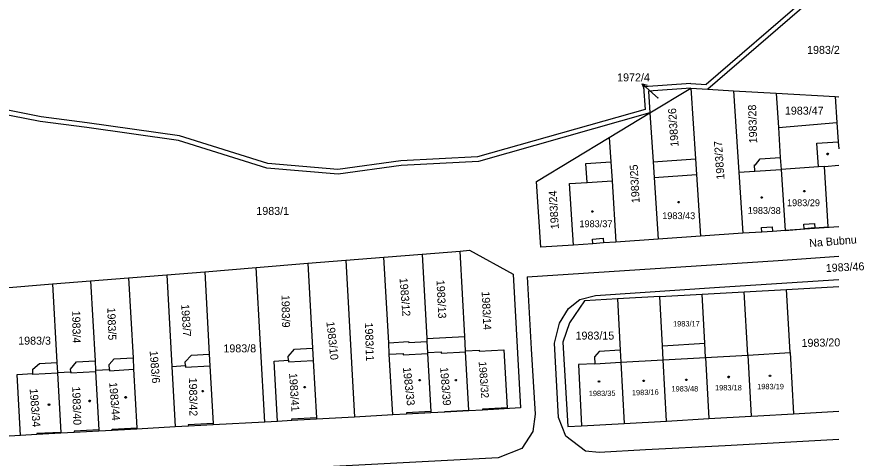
# Model space of a CAD drawing. Extents: x -621797 to -620972, y -1175539 to -1174697.
# Drawn here: x -621151.7 to -620971.8, y -1174978.1 to -1174884.4 of the extents above; entities that cross this region are included whole.
import ezdxf

# ---------------------------------------------------------------- set-up
doc = ezdxf.new("R2010")
doc.units = 0
for name, color, linetype in [('INZ mimo EON - nadz', 7, 'Continuous'), ('Rozvod plynu EON', 7, 'Continuous'), ('SDEL EON - popis', 7, 'Continuous'), ('Silnoproud EON', 7, 'Continuous'), ('Silnoproud EON - popis', 7, 'Continuous')]:
    doc.layers.add(name, color=color, linetype=linetype)

msp = doc.modelspace()

# ---------------------------------------------------------------- linework, layer by layer
at = {"layer": 'INZ mimo EON - nadz'}
for p in [(-621018.904, -1174898.566), (-621015.51, -1174901.63)]:
    msp.add_line(p, (-621016.68, -1174900.58), dxfattribs=at)
msp.add_lwpolyline([(-621018.498, -1174899.608), (-621018.904, -1174898.566), (-621017.827, -1174898.867)], dxfattribs=at)
at = {"layer": 'Rozvod plynu EON'}
for points in [[(-620979.43, -1174913.35), (-620979.34, -1174913.5), (-620979.43, -1174913.65), (-620979.61, -1174913.65), (-620979.7, -1174913.5), (-620979.61, -1174913.35)], [(-620984.37, -1174921.26), (-620984.28, -1174921.41), (-620984.37, -1174921.56), (-620984.55, -1174921.56), (-620984.64, -1174921.41), (-620984.55, -1174921.26)], [(-621011.08, -1174923.58), (-621010.99, -1174923.73), (-621011.08, -1174923.88), (-621011.26, -1174923.88), (-621011.35, -1174923.73), (-621011.26, -1174923.58)], [(-620993.39, -1174922.61), (-620993.3, -1174922.76), (-620993.39, -1174922.91), (-620993.57, -1174922.91), (-620993.66, -1174922.76), (-620993.57, -1174922.61)], [(-621029.36, -1174925.58), (-621029.27, -1174925.73), (-621029.36, -1174925.88), (-621029.54, -1174925.88), (-621029.63, -1174925.73), (-621029.54, -1174925.58)], [(-621066.05, -1174961.4), (-621065.96, -1174961.55), (-621066.05, -1174961.7), (-621066.23, -1174961.7), (-621066.32, -1174961.55), (-621066.23, -1174961.4)], [(-621058.36, -1174961.4), (-621058.27, -1174961.55), (-621058.36, -1174961.7), (-621058.54, -1174961.7), (-621058.63, -1174961.55), (-621058.54, -1174961.4)], [(-621027.97, -1174961.73), (-621027.88, -1174961.88), (-621027.97, -1174962.03), (-621028.15, -1174962.03), (-621028.24, -1174961.88), (-621028.15, -1174961.73)], [(-621018.5, -1174961.55), (-621018.41, -1174961.7), (-621018.5, -1174961.85), (-621018.68, -1174961.85), (-621018.77, -1174961.7), (-621018.68, -1174961.55)], [(-621009.43, -1174961.36), (-621009.34, -1174961.51), (-621009.43, -1174961.66), (-621009.61, -1174961.66), (-621009.7, -1174961.51), (-621009.61, -1174961.36)], [(-621000.46, -1174960.76), (-621000.37, -1174960.91), (-621000.46, -1174961.06), (-621000.64, -1174961.06), (-621000.73, -1174960.91), (-621000.64, -1174960.76)], [(-620991.67, -1174960.48), (-620991.58, -1174960.63), (-620991.67, -1174960.78), (-620991.85, -1174960.78), (-620991.94, -1174960.63), (-620991.85, -1174960.48)], [(-621090.5, -1174962.94), (-621090.41, -1174963.09), (-621090.5, -1174963.24), (-621090.68, -1174963.24), (-621090.77, -1174963.09), (-621090.68, -1174962.94)], [(-621128.5, -1174965.07), (-621128.41, -1174965.22), (-621128.5, -1174965.37), (-621128.68, -1174965.37), (-621128.77, -1174965.22), (-621128.68, -1174965.07)], [(-621112.12, -1174963.75), (-621112.03, -1174963.9), (-621112.12, -1174964.05), (-621112.3, -1174964.05), (-621112.39, -1174963.9), (-621112.3, -1174963.75)], [(-621144.78, -1174966.63), (-621144.69, -1174966.78), (-621144.78, -1174966.93), (-621144.96, -1174966.93), (-621145.05, -1174966.78), (-621144.96, -1174966.63)], [(-621136.17, -1174965.86), (-621136.08, -1174966.01), (-621136.17, -1174966.16), (-621136.35, -1174966.16), (-621136.44, -1174966.01), (-621136.35, -1174965.86)]]:
    msp.add_lwpolyline(points, close=True, dxfattribs=at)
at = {"layer": 'SDEL EON - popis'}
for p, q in [((-620984.41, -1174880.64), (-621005.32, -1174898.72)), ((-621008.55, -1174898.53), (-621018.59, -1174899.19)), ((-621008.55, -1174898.53), (-621005.32, -1174898.72)), ((-621018.59, -1174899.19), (-621018.28, -1174904.03)), ((-621146.57, -1174905.58), (-621155.92, -1174903.76)), ((-621018.28, -1174904.03), (-621053.84, -1174914.11)), ((-621136.73, -1174906.87), (-621146.57, -1174905.58)), ((-621117.18, -1174909.65), (-621136.73, -1174906.87)), ((-621098.42, -1174915.51), (-621117.18, -1174909.65)), ((-620981.79, -1174911.23), (-620977.25, -1174910.88)), ((-620981.41, -1174916.22), (-620981.79, -1174911.23)), ((-621070.16, -1174914.95), (-621083.51, -1174916.76)), ((-621053.84, -1174914.11), (-621070.16, -1174914.95)), ((-621083.51, -1174916.76), (-621098.42, -1174915.51)), ((-620981.41, -1174916.22), (-620989.38, -1174916.78)), ((-620980.2, -1174916.14), (-620981.41, -1174916.22)), ((-620980.2, -1174916.14), (-620977.15, -1174915.88)), ((-620979.37, -1174928.97), (-620980.2, -1174916.14)), ((-621016.33, -1174918.48), (-621007.35, -1174917.88)), ((-620994.97, -1174917.16), (-620989.38, -1174916.78)), ((-621030.58, -1174919.54), (-621025.29, -1174919.2)), ((-620993.52, -1174929.1), (-620991.29, -1174928.95)), ((-620993.45, -1174930.09), (-620993.52, -1174929.1)), ((-620991.29, -1174928.95), (-620991.22, -1174929.95)), ((-620984.58, -1174928.44), (-620982.29, -1174928.26)), ((-620984.5, -1174929.42), (-620984.58, -1174928.44)), ((-620982.21, -1174929.22), (-620984.5, -1174929.42)), ((-620982.29, -1174928.26), (-620982.21, -1174929.22)), ((-620982.21, -1174929.22), (-620979.37, -1174928.97)), ((-620988.53, -1174929.77), (-620984.5, -1174929.42)), ((-621029.46, -1174931.57), (-621027.18, -1174931.42)), ((-621029.39, -1174932.57), (-621029.46, -1174931.57)), ((-621027.18, -1174931.42), (-621027.12, -1174932.41)), ((-621072.59, -1174956.04), (-621069.66, -1174955.88)), ((-621069.66, -1174955.88), (-621069.65, -1174956.22)), ((-621069.65, -1174956.22), (-621064.48, -1174955.93)), ((-621064.49, -1174955.73), (-621061.56, -1174955.58)), ((-621061.56, -1174955.58), (-621061.55, -1174955.84)), ((-621061.55, -1174955.84), (-621056.4, -1174955.53)), ((-621005.44, -1174956.73), (-620996.47, -1174956.23)), ((-620996.47, -1174956.23), (-620987.48, -1174955.73)), ((-621094.02, -1174957.36), (-621094, -1174957.71)), ((-621094, -1174957.71), (-621088.74, -1174957.42)), ((-621028.96, -1174958.09), (-621023.42, -1174957.78)), ((-621023.42, -1174957.78), (-621014.43, -1174957.26)), ((-621014.43, -1174957.26), (-621005.44, -1174956.73)), ((-621140.26, -1174959.77), (-621140.24, -1174960.03)), ((-621140.24, -1174960.03), (-621134.98, -1174959.74)), ((-621132.04, -1174959.28), (-621132.03, -1174959.58)), ((-621132.03, -1174959.58), (-621126.89, -1174959.25)), ((-621115.91, -1174958.49), (-621115.9, -1174958.79)), ((-621115.9, -1174958.79), (-621110.71, -1174958.5)), ((-621148.27, -1174960.4), (-621148.28, -1174960.15)), ((-621143.07, -1174960.11), (-621148.27, -1174960.4)), ((-621063.8, -1174968.23), (-621068.96, -1174968.51)), ((-621068.96, -1174968.51), (-621068.94, -1174968.81)), ((-621060.82, -1174968.22), (-621055.71, -1174967.93)), ((-621060.82, -1174968.36), (-621060.82, -1174968.22)), ((-621088.07, -1174969.57), (-621093.34, -1174969.86)), ((-621093.34, -1174969.86), (-621093.32, -1174970.16)), ((-621134.3, -1174972.13), (-621139.51, -1174972.42)), ((-621139.51, -1174972.42), (-621139.5, -1174972.71)), ((-621131.46, -1174971.97), (-621126.21, -1174971.68)), ((-621131.45, -1174972.27), (-621131.46, -1174971.97)), ((-621110.04, -1174970.78), (-621115.28, -1174971.08)), ((-621115.28, -1174971.08), (-621115.27, -1174971.37)), ((-621142.38, -1174972.67), (-621147.47, -1174972.88)), ((-621147.47, -1174972.88), (-621147.46, -1174973.15))]:
    msp.add_line(p, q, dxfattribs=at)
at = {"layer": 'Silnoproud EON'}
for p, q in [((-620983.45, -1174881.13), (-621004.97, -1174899.74)), ((-621008.55, -1174899.53), (-621017.53, -1174900.12)), ((-621017.53, -1174900.12), (-621017.23, -1174904.77)), ((-621017.23, -1174904.77), (-621008.55, -1174899.53)), ((-621008.55, -1174899.53), (-621004.97, -1174899.74)), ((-621008.55, -1174899.53), (-621007.57, -1174914.56)), ((-621004.97, -1174899.74), (-620999.5, -1174900.06)), ((-620999.5, -1174900.06), (-620990.45, -1174900.58)), ((-620999.5, -1174900.06), (-620998.36, -1174917.38)), ((-620990.45, -1174900.58), (-620977.89, -1174901.3)), ((-620990.45, -1174900.58), (-620989.97, -1174907.83)), ((-620977.89, -1174901.3), (-620977.15, -1174901.342)), ((-620977.89, -1174901.3), (-620977.52, -1174906.82)), ((-621146.73, -1174906.57), (-621156.07, -1174904.75)), ((-621017.23, -1174904.77), (-621053.68, -1174915.1)), ((-621025.89, -1174910), (-621017.23, -1174904.77)), ((-621017.23, -1174904.77), (-621016.55, -1174915.19)), ((-621136.87, -1174907.86), (-621146.73, -1174906.57)), ((-620989.97, -1174907.83), (-620977.52, -1174906.82)), ((-620977.52, -1174906.82), (-620977.25, -1174910.88)), ((-621117.4, -1174910.63), (-621136.87, -1174907.86)), ((-620989.97, -1174907.83), (-620989.55, -1174914.24)), ((-621098.61, -1174916.5), (-621117.4, -1174910.63)), ((-621041.3, -1174919.31), (-621025.89, -1174910)), ((-621025.89, -1174910), (-621025.56, -1174915.16)), ((-620977.25, -1174910.88), (-620977.15, -1174912.389)), ((-621016.55, -1174915.19), (-621007.57, -1174914.56)), ((-621007.57, -1174914.56), (-621007.35, -1174917.88)), ((-620994.81, -1174915.81), (-620993.81, -1174914.52)), ((-620993.81, -1174914.52), (-620989.55, -1174914.24)), ((-620989.55, -1174914.24), (-620989.38, -1174916.78)), ((-621083.48, -1174917.77), (-621098.61, -1174916.5)), ((-621070.07, -1174915.95), (-621083.48, -1174917.77)), ((-621053.68, -1174915.1), (-621070.07, -1174915.95)), ((-621030.85, -1174915.5), (-621025.56, -1174915.16)), ((-621030.58, -1174919.54), (-621030.85, -1174915.5)), ((-621025.56, -1174915.16), (-621025.29, -1174919.2)), ((-621016.55, -1174915.19), (-621016.33, -1174918.48)), ((-620995.06, -1174915.83), (-620994.81, -1174915.81)), ((-620994.97, -1174917.16), (-620995.06, -1174915.83)), ((-621016.33, -1174918.48), (-621015.47, -1174931.62)), ((-621007.35, -1174917.88), (-621006.49, -1174930.97)), ((-620998.36, -1174917.38), (-620994.97, -1174917.16)), ((-620998.36, -1174917.38), (-620997.51, -1174930.36)), ((-620989.38, -1174916.78), (-620988.53, -1174929.77)), ((-621040.42, -1174933.33), (-621041.3, -1174919.31)), ((-621034.34, -1174919.78), (-621030.58, -1174919.54)), ((-621033.48, -1174932.85), (-621034.34, -1174919.78)), ((-621025.29, -1174919.2), (-621024.45, -1174932.23)), ((-620977.15, -1174928.986), (-620988.53, -1174929.77)), ((-621006.49, -1174930.97), (-621015.47, -1174931.62)), ((-620997.51, -1174930.36), (-621006.49, -1174930.97)), ((-620993.45, -1174930.09), (-620997.51, -1174930.36)), ((-620991.22, -1174929.95), (-620993.45, -1174930.09)), ((-620988.53, -1174929.77), (-620991.22, -1174929.95)), ((-621033.48, -1174932.85), (-621040.42, -1174933.33)), ((-621029.39, -1174932.57), (-621033.48, -1174932.85)), ((-621027.12, -1174932.41), (-621029.39, -1174932.57)), ((-621024.45, -1174932.23), (-621027.12, -1174932.41)), ((-621015.47, -1174931.62), (-621024.45, -1174932.23)), ((-621065.65, -1174934.79), (-621057.58, -1174934.13)), ((-621057.58, -1174934.13), (-621055.58, -1174933.97)), ((-621056.58, -1174952.3), (-621057.58, -1174934.13)), ((-621055.58, -1174933.97), (-621046.29, -1174939.02)), ((-621089.88, -1174936.74), (-621081.8, -1174936.09)), ((-621081.8, -1174936.09), (-621073.73, -1174935.45)), ((-621081.8, -1174936.09), (-621079.96, -1174969.42)), ((-621073.73, -1174935.45), (-621065.65, -1174934.79)), ((-621072.72, -1174953.63), (-621073.73, -1174935.45)), ((-621065.65, -1174934.79), (-621064.66, -1174952.71)), ((-621043.3, -1174939.63), (-620989.98, -1174936.11)), ((-620989.98, -1174936.11), (-620977.15, -1174935.228)), ((-621111.81, -1174938.52), (-621100.85, -1174937.63)), ((-621100.85, -1174937.63), (-621089.88, -1174936.74)), ((-621099.03, -1174970.48), (-621100.85, -1174937.63)), ((-621089.88, -1174936.74), (-621088.88, -1174954.78)), ((-621136.04, -1174940.48), (-621127.96, -1174939.83)), ((-621127.96, -1174939.83), (-621119.88, -1174939.17)), ((-621127.96, -1174939.83), (-621127.02, -1174956.85)), ((-621119.88, -1174939.17), (-621111.81, -1174938.52)), ((-621119.88, -1174939.17), (-621118.81, -1174958.65)), ((-621111.81, -1174938.52), (-621110.85, -1174956.05)), ((-621046.29, -1174939.02), (-621044.72, -1174967.47)), ((-621043.3, -1174939.63), (-621042.46, -1174954.9)), ((-621155.09, -1174942.02), (-621144.12, -1174941.13)), ((-621144.12, -1174941.13), (-621136.04, -1174940.48)), ((-621144.12, -1174941.13), (-621143.2, -1174957.8)), ((-621136.04, -1174940.48), (-621135.1, -1174957.44)), ((-621028.81, -1174943.58), (-621002.46, -1174941.84)), ((-621002.46, -1174941.84), (-620977.15, -1174940.162)), ((-620988.22, -1174942.27), (-620977.15, -1174941.631)), ((-621032.11, -1174944.44), (-621028.81, -1174943.58)), ((-621015.17, -1174943.81), (-621006.18, -1174943.3)), ((-621006.18, -1174943.3), (-620997.21, -1174942.78)), ((-621005.61, -1174953.73), (-621006.18, -1174943.3)), ((-620997.21, -1174942.78), (-620988.22, -1174942.27)), ((-620996.47, -1174956.23), (-620997.21, -1174942.78)), ((-620987.48, -1174955.73), (-620988.22, -1174942.27)), ((-621034.54, -1174946.32), (-621032.11, -1174944.44)), ((-621031.14, -1174944.71), (-621034.35, -1174949.41)), ((-621024.16, -1174944.31), (-621031.14, -1174944.71)), ((-621015.17, -1174943.81), (-621024.16, -1174944.31)), ((-621024.16, -1174944.31), (-621023.56, -1174955.21)), ((-621014.6, -1174954.25), (-621015.17, -1174943.81)), ((-621036.43, -1174949.44), (-621034.54, -1174946.32)), ((-621037.52, -1174953.74), (-621036.43, -1174949.44)), ((-621034.35, -1174949.41), (-621035.71, -1174953.47)), ((-621064.66, -1174952.71), (-621056.58, -1174952.3)), ((-621064.66, -1174952.71), (-621064.63, -1174953.35)), ((-621056.41, -1174955.33), (-621056.58, -1174952.3)), ((-621072.72, -1174953.63), (-621068.49, -1174953.36)), ((-621072.59, -1174956.04), (-621072.72, -1174953.63)), ((-621068.49, -1174953.36), (-621068.46, -1174953.56)), ((-621068.46, -1174953.56), (-621064.63, -1174953.35)), ((-621064.63, -1174953.35), (-621064.49, -1174955.73)), ((-621036.68, -1174969.5), (-621037.52, -1174953.74)), ((-621035.71, -1174953.47), (-621034.69, -1174971.44)), ((-621014.6, -1174954.25), (-621005.61, -1174953.73)), ((-621014.43, -1174957.26), (-621014.6, -1174954.25)), ((-621005.44, -1174956.73), (-621005.61, -1174953.73)), ((-621115.96, -1174957.71), (-621114.61, -1174956.25)), ((-621114.61, -1174956.25), (-621110.85, -1174956.05)), ((-621110.85, -1174956.05), (-621110.71, -1174958.5)), ((-621094.06, -1174956.58), (-621092.7, -1174954.99)), ((-621092.7, -1174954.99), (-621088.88, -1174954.78)), ((-621088.88, -1174954.78), (-621088.74, -1174957.42)), ((-621071.88, -1174968.97), (-621072.59, -1174956.04)), ((-621064.49, -1174955.73), (-621064.48, -1174955.93)), ((-621064.48, -1174955.93), (-621063.8, -1174968.23)), ((-621056.41, -1174955.33), (-621053.54, -1174955.17)), ((-621056.4, -1174955.53), (-621056.41, -1174955.33)), ((-621055.71, -1174967.93), (-621056.4, -1174955.53)), ((-621053.54, -1174955.17), (-621053.53, -1174955.41)), ((-621053.53, -1174955.41), (-621048.25, -1174955.12)), ((-621048.25, -1174955.12), (-621047.54, -1174967.48)), ((-621042.46, -1174954.9), (-621041.64, -1174968.78)), ((-621028.05, -1174955.46), (-621029.04, -1174956.61)), ((-621023.56, -1174955.21), (-621028.05, -1174955.46)), ((-621023.56, -1174955.21), (-621023.42, -1174957.78)), ((-620996.47, -1174956.23), (-620995.75, -1174969.24)), ((-620987.48, -1174955.73), (-620986.76, -1174968.73)), ((-621148.33, -1174959.24), (-621146.92, -1174958.01)), ((-621146.92, -1174958.01), (-621143.2, -1174957.8)), ((-621143.2, -1174957.8), (-621143.08, -1174959.93)), ((-621140.29, -1174959.22), (-621139.05, -1174957.66)), ((-621139.05, -1174957.66), (-621135.1, -1174957.44)), ((-621135.1, -1174957.44), (-621135, -1174959.44)), ((-621132.1, -1174958.22), (-621131.02, -1174957.07)), ((-621131.02, -1174957.07), (-621127.02, -1174956.85)), ((-621127.02, -1174956.85), (-621126.89, -1174959.25)), ((-621115.91, -1174958.49), (-621115.96, -1174957.71)), ((-621097.02, -1174957.53), (-621094.02, -1174957.36)), ((-621096.36, -1174970.33), (-621097.02, -1174957.53)), ((-621094.02, -1174957.36), (-621094.06, -1174956.58)), ((-621088.74, -1174957.42), (-621088.07, -1174969.57)), ((-621028.96, -1174958.09), (-621032.44, -1174958.23)), ((-621029.04, -1174956.61), (-621028.96, -1174958.09)), ((-621023.42, -1174957.78), (-621022.71, -1174970.76)), ((-621013.72, -1174970.27), (-621014.43, -1174957.26)), ((-621005.44, -1174956.73), (-621004.73, -1174969.76)), ((-621148.28, -1174960.15), (-621148.33, -1174959.24)), ((-621143.08, -1174959.93), (-621140.26, -1174959.77)), ((-621143.08, -1174959.93), (-621143.07, -1174960.11)), ((-621140.26, -1174959.77), (-621140.29, -1174959.22)), ((-621135, -1174959.44), (-621132.04, -1174959.28)), ((-621135, -1174959.44), (-621134.98, -1174959.74)), ((-621134.98, -1174959.74), (-621134.3, -1174972.13)), ((-621132.04, -1174959.28), (-621132.1, -1174958.22)), ((-621126.89, -1174959.25), (-621126.21, -1174971.68)), ((-621118.81, -1174958.65), (-621115.91, -1174958.49)), ((-621118.81, -1174958.65), (-621118.1, -1174971.53)), ((-621110.71, -1174958.5), (-621110.04, -1174970.78)), ((-621032.44, -1174958.23), (-621031.76, -1174971.28)), ((-621151.64, -1174960.36), (-621148.28, -1174960.15)), ((-621150.91, -1174973.34), (-621151.64, -1174960.36)), ((-621143.07, -1174960.11), (-621142.38, -1174972.67)), ((-621068.94, -1174968.81), (-621071.88, -1174968.97)), ((-621063.79, -1174968.53), (-621068.94, -1174968.81)), ((-621063.8, -1174968.23), (-621063.79, -1174968.53)), ((-621060.82, -1174968.36), (-621063.79, -1174968.53)), ((-621055.7, -1174968.08), (-621060.82, -1174968.36)), ((-621055.7, -1174968.08), (-621055.71, -1174967.93)), ((-621052.81, -1174967.92), (-621055.7, -1174968.08)), ((-621047.54, -1174967.48), (-621052.82, -1174967.77)), ((-621052.82, -1174967.77), (-621052.81, -1174967.92)), ((-621044.72, -1174967.47), (-621052.81, -1174967.92)), ((-621041.64, -1174968.78), (-621042.1, -1174972.5)), ((-620994.35, -1174969.16), (-620986.76, -1174968.73)), ((-620986.76, -1174968.73), (-620977.15, -1174968.176)), ((-621099.03, -1174970.48), (-621110.02, -1174971.08)), ((-621096.36, -1174970.33), (-621099.03, -1174970.48)), ((-621093.32, -1174970.16), (-621096.36, -1174970.33)), ((-621088.05, -1174969.87), (-621093.32, -1174970.16)), ((-621088.07, -1174969.57), (-621088.05, -1174969.87)), ((-621079.96, -1174969.42), (-621088.05, -1174969.87)), ((-621071.88, -1174968.97), (-621079.96, -1174969.42)), ((-621035.13, -1174973.46), (-621036.68, -1174969.5)), ((-621022.71, -1174970.76), (-621013.72, -1174970.27)), ((-621013.72, -1174970.27), (-621004.73, -1174969.76)), ((-621004.73, -1174969.76), (-620995.75, -1174969.24)), ((-620995.75, -1174969.24), (-620994.35, -1174969.16)), ((-621134.28, -1174972.42), (-621139.5, -1174972.71)), ((-621134.3, -1174972.13), (-621134.28, -1174972.42)), ((-621131.45, -1174972.27), (-621134.28, -1174972.42)), ((-621126.19, -1174971.97), (-621131.45, -1174972.27)), ((-621126.21, -1174971.68), (-621126.19, -1174971.97)), ((-621118.1, -1174971.53), (-621126.19, -1174971.97)), ((-621115.27, -1174971.37), (-621118.1, -1174971.53)), ((-621110.02, -1174971.08), (-621115.27, -1174971.37)), ((-621110.04, -1174970.78), (-621110.02, -1174971.08)), ((-621042.1, -1174972.5), (-621044.48, -1174976.1)), ((-621034.69, -1174971.44), (-621031.76, -1174971.28)), ((-621031.76, -1174971.28), (-621022.71, -1174970.76)), ((-621150.91, -1174973.34), (-621153.35, -1174973.48)), ((-621147.46, -1174973.15), (-621150.91, -1174973.34)), ((-621142.37, -1174972.87), (-621147.46, -1174973.15)), ((-621142.38, -1174972.67), (-621142.37, -1174972.87)), ((-621139.5, -1174972.71), (-621142.37, -1174972.87)), ((-621030.92, -1174976.66), (-621035.13, -1174973.46)), ((-620977.15, -1174974.155), (-621001.28, -1174975.51)), ((-621044.48, -1174976.1), (-621049.45, -1174978.08)), ((-621001.28, -1174975.51), (-621018.2, -1174976.41)), ((-621028.03, -1174976.94), (-621030.92, -1174976.66)), ((-621018.2, -1174976.41), (-621028.03, -1174976.94)), ((-621049.45, -1174978.08), (-621095.2, -1174980.47))]:
    msp.add_line(p, q, dxfattribs=at)

# ---------------------------------------------------------------- texts
at = {"layer": 'INZ mimo EON - nadz'}
msp.add_text('1972/4', height=1.7, dxfattribs=at).set_placement((-621024.208, -1174898.06))
msp.add_text('Na Bubnu', height=1.7, rotation=4.64096, dxfattribs=at).set_placement((-620983.347, -1174933.308))
at = {"layer": 'Silnoproud EON - popis'}
for s, height, p in [('1983/2', 1.7, (-620983.867, -1174892.22)), ('1972/4', 0.1, (-621015.734, -1174901.63)), ('1983/47', 1.7, (-620988.577, -1174905.13)), ('1983/29', 1.45, (-620988.137, -1174924.59)), ('1983/1', 1.7, (-621100.837, -1174926.45)), ('1983/17', 1.14, (-621012.337, -1174950.16)), ('1983/3', 1.7, (-621151.417, -1174954.03)), ('1983/15', 1.7, (-621033.037, -1174952.95)), ('1983/8', 1.7, (-621107.827, -1174955.67)), ('1983/48', 1.14, (-621012.673, -1174963.98)), ('1983/18', 1.14, (-621003.42, -1174963.75)), ('1983/19', 1.14, (-620994.476, -1174963.5))]:
    msp.add_text(s, height=height, dxfattribs=at).set_placement(p)
for s, height, rotation, p in [('1983/26', 1.7, 94.02238, (-621011.138, -1174911.888)), ('1983/28', 1.7, 91.78784, (-620994.452, -1174911.197)), ('1983/27', 1.7, 93.96508, (-621001.387, -1174918.878)), ('1983/25', 1.7, 93.10564, (-621019.411, -1174923.888)), ('1983/24', 1.7, 93.6213, (-621036.565, -1174929.428)), ('1983/38', 1.45, 359.41643, (-620996.475, -1174926.193)), ('1983/37', 1.45, 0.05729, (-621032.215, -1174929.06)), ('1983/43', 1.45, 359.93209, (-621014.635, -1174927.34)), ('1983/46', 1.7, 2.86479, (-620979.858, -1174938.6)), ('1983/12', 1.7, 274.50408, (-621070.429, -1174939.891)), ('1983/13', 1.7, 272.72791, (-621062.571, -1174940.302)), ('1983/9', 1.7, 270.89444, (-621095.484, -1174943.463)), ('1983/14', 1.7, 272.72791, (-621052.981, -1174942.742)), ('1983/4', 1.7, 270.89444, (-621139.944, -1174946.813)), ('1983/5', 1.7, 271.81118, (-621132.488, -1174946.173)), ('1983/7', 1.7, 273.58735, (-621116.805, -1174945.472)), ('1983/10', 1.7, 276.28025, (-621085.967, -1174949.19)), ('1983/11', 1.7, 271.81118, (-621077.788, -1174949.353)), ('1983/20', 1.7, 0.91673, (-620985.027, -1174954.514)), ('1983/6', 1.7, 274.50408, (-621123.499, -1174955.381)), ('1983/32', 1.62, 274.33219, (-621053.621, -1174957.658)), ('1983/33', 1.7, 276.28025, (-621069.717, -1174958.9)), ('1983/39', 1.7, 274.50408, (-621061.809, -1174958.861)), ('1983/42', 1.7, 270.89444, (-621115.154, -1174961.043)), ('1983/41', 1.7, 273.58735, (-621093.885, -1174960.102)), ('1983/34', 1.7, 274.50408, (-621148.989, -1174963.421)), ('1983/40', 1.7, 271.81118, (-621139.948, -1174962.943)), ('1983/44', 1.7, 274.50408, (-621132.089, -1174962.061)), ('1983/16', 1.14, 1.66158, (-621021.057, -1174964.822)), ('1983/35', 1.14, 0.51566, (-621030.237, -1174964.978))]:
    msp.add_text(s, height=height, rotation=rotation, dxfattribs=at).set_placement(p)

doc.saveas('drawing.dxf')
